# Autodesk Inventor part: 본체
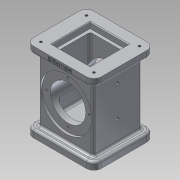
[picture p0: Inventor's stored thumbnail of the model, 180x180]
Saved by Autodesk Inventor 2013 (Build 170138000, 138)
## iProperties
Created: 2017-08
Part Number: 본체
Material: 알루미늄 6061
Document SubType Name: Modeling
Designer: Administrator
Density: 2.71 g/cm^3
Mass: 843.232 g
Surface Area: 643.489 cm^2
Volume: 311.156 cm^3
Author: Administrator
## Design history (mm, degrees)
sketch "스케치4"
  geometry: L1 (0, 0)-(-74, 0); L2 (-74, 0)-(-74, 88); L3 (-74, 88)-(0, 88); L4 (0, 88)-(0, 0)
  constraints: 8 end point, 2 parallel, 1 horizontal, 1 perpendicular
  dimensions: "d26" = 88 distance of L3.end L1.start; "d27" = 74 distance of L2.end L3.end
extrude "돌출1" new body sketch "스케치4" distance "d28" = 66; taper "d29" = 0 deg
sketch "스케치5"
  geometry: L1 (74, 0)-(0, 0) reference; L2 (74, 0)-(74, 66) reference; L3 (83, -8)-(-9, -8); L4 (-9, 74)-(83, 74); L5 (-9, 74)-(-9, -8); L6 (83, -8)-(83, 74)
  constraints: 8 end point, 1 parallel, 1 perpendicular
  dimensions: "d127" = 92 distance of L4.start L4.end; "d128" = 82 distance of L3.start L4.end; "d129" = 8 distance between parallel lines of L3 L1; "d130" = 9 distance between parallel lines of L6 L2
extrude "돌출2" join sketch "스케치5" distance "d31" = 10; taper "d32" = 0 deg
sketch "스케치6"
  geometry: L1 (0, 66)-(74, 66) reference; L2 (83, 74)-(83, -8); L3 (-9, -8)-(-9, 74); L4 (-9, 74)-(83, 74); L5 (-9, -8)-(83, -8); L6 (74, 0)-(74, 66) reference
  constraints: 8 end point, 1 parallel, 1 perpendicular
  dimensions: "d133" = 82 distance of L2.start L2.end; "d135" = 92 distance of L3.end L2.start; "d136" = 8 distance between parallel lines of L1 L4; "d142" = 9 distance between parallel lines of L2 L6
extrude "돌출3" join sketch "스케치6" distance "d34" = 10; taper "d35" = 0 deg
fillet "모깎기1" dims "d36" = 3, "d53" = 10
sketch "스케치7"
  geometry: L1 (0, 88)-(0, 0) reference; L2 (1, 98)-(73, 98) reference; C1 r 35 at (37, 44)
  constraints: 1 centre point
  dimensions: "d37" = 37 distance from line of L1 C1.centre; "d38" = 54 distance from line of L2 C1.centre; "d39" = 70 diameter of C1
extrude "돌출4" cut sketch "스케치7" distance "d40" = 3; taper "d41" = 0 deg
sketch "스케치8"
  geometry: C1 r 35 at (37, -44) reference; C2 r 35 at (37, -44)
  constraints: 1 centre point, 1 coincident, 1 concentric
extrude "돌출5" cut sketch "스케치8" distance "d42" = 3; taper "d43" = 0 deg
sketch "스케치9"
  geometry: C1 r 35 at (0, 0) reference; C2 r 24 at (0, 0); 1 further point
  constraints: 1 centre point, 1 coincident
  dimensions: "d44" = 48 diameter of C2
extrude "돌출6" cut sketch "스케치9" stored distance "d46" = 3; taper "d47" = 0 deg
sketch "스케치10"
  geometry: L1 (73, 74)-(1, 74) reference; L2 (11, 59)-(63, 59); L3 (63, 59)-(63, 7); L4 (63, 7)-(11, 7); L5 (11, 7)-(11, 59); L6 (-9, 64)-(-9, 2) reference; 1 further point
  constraints: 8 end point, 2 parallel, 1 horizontal, 1 perpendicular
  dimensions: "d48" = 52 distance of L2.start L2.end; "d50" = 52 distance of L2.end L3.end; "d126" = 15 distance between parallel lines of L2 L1; "d131" = 20 distance between parallel lines of L6 L5
extrude "돌출7" cut sketch "스케치10" distance "d54" = 8; taper "d55" = 0 deg
sketch "스케치11"
  geometry: L1 (11, 59)-(63, 59) reference; L2 (11, 7)-(11, 59) reference; L3 (63, 7)-(11, 7) reference; L4 (63, 59)-(63, 7) reference; L5 (59, 55)-(15, 55); L6 (15, 55)-(15, 11); L7 (15, 11)-(59, 11); L8 (59, 11)-(59, 55); 1 further point
  constraints: 8 end point, 3 other
  dimensions: "d56" = 4 distance between parallel lines of L5 L1
extrude "돌출8" cut sketch "스케치11" distance "d57" = 74; taper "d58" = 0 deg
fillet "모깎기2" dims "d59" = 3
sketch "스케치12"
  geometry: 20 further points
  constraints: 4 coincident, 4 other
hole "구멍1" sketch "스케치12" at (1, 64), (73, 64), (73, 2), (1, 2) diameter "d60" = 3.242; stored, may be unused: countersink angle "d64" = 90 deg, drill point angle "d66" = 118 deg; dims "d61" = 4, "d62" = 4, "d63" = 2, "d65" = 6
sketch "스케치13"
  geometry: 20 further points
  constraints: 4 coincident, 4 other
hole "구멍2" sketch "스케치13" at (1, 64), (73, 64), (73, 2), (1, 2) diameter "d67" = 3.242; stored, may be unused: countersink angle "d71" = 90 deg, drill point angle "d73" = 118 deg; dims "d68" = 4, "d69" = 4, "d70" = 2, "d72" = 6
sketch "스케치14" dims "d74" = 58
  geometry: C1 r 24 at (0, 0) reference; C2 r 35 at (0, 0) reference; 3 further points
  constraints: 1 coincident, 1 vertical alignment, 2 other
  dimensions: "d76" = 0 horizontal distance of C1.centre point (0, 29)
hole "구멍3" sketch "스케치14" at (0, 29) diameter "d77" = 3.242; stored, may be unused: countersink angle "d81" = 90 deg, drill point angle "d83" = 118 deg; dims "d78" = 4, "d79" = 4, "d80" = 2, "d82" = 6
chamfer "모따기1" distance "d87" = 1; stored, may be unused: second distance "d88" = 2, angle "d89" = 45 deg
sketch "스케치15" dims "d90" = 58
  geometry: C1 r 24 at (0, 0) reference; C2 r 35 at (0, 0) reference; 3 further points
  constraints: 1 coincident, 1 vertical alignment, 2 other
  dimensions: "d92" = 0 horizontal distance of C1.centre point (0, -29)
hole "구멍4" sketch "스케치15" at (0, -29) diameter "d93" = 3.242; stored, may be unused: countersink angle "d97" = 90 deg, drill point angle "d99" = 118 deg; dims "d94" = 4, "d95" = 4, "d96" = 2, "d98" = 6
sketch "스케치16"
  geometry: L1 (88, 0)-(0, 0) reference; L2 (98, 64)-(98, 2) reference; 2 further points
  dimensions: "d100" = 33 distance from line of point (18, 33) L1; "d101" = 33 distance from line of L1 point (60, 33); "d102" = 38 distance from line of L2 point (60, 33); "d103" = 42 distance of point (60, 33) point (18, 33)
hole "구멍5" sketch "스케치16" at (18, 33), (60, 33) diameter "d104" = 4.134; stored, may be unused: countersink angle "d108" = 90 deg, drill point angle "d110" = 118 deg; dims "d105" = 4, "d106" = 4, "d107" = 2, "d109" = 20
sketch "스케치17"
  geometry: L1 (83, 2)-(83, 64) reference; L2 (61, 9)-(13, 9); L3 (13, 9)-(13, 57); L4 (13, 57)-(61, 57); L5 (61, 57)-(61, 9); L6 (1, -8)-(73, -8) reference
  constraints: 8 end point, 2 parallel, 1 horizontal, 1 perpendicular
  dimensions: "d111" = 48 distance of L2.start L2.end; "d113" = 48 distance of L2.end L3.end; "d115" = 22 distance between parallel lines of L5 L1; "d137" = 17 distance between parallel lines of L6 L2
extrude "돌출9" cut sketch "스케치17" distance "d116" = 16; taper "d117" = 0 deg
fillet "모깎기3" dims "d118" = 3
sketch "스케치18"
  geometry: L1 (0, 0)-(72, 0) reference; L2 (16.555, 0.528)-(55.445, 0.528); L3 (55.445, 0.528)-(55.445, -8.528); L4 (55.445, -8.528)-(16.555, -8.528); L5 (16.555, -8.528)-(16.555, 0.528); L6 (36, 0.528)-(36, -8.528); L7 (16.555, -4)-(55.445, -4); L8 (-10, 0)-(-10, -10) reference; 1 further point
  constraints: 4 end point, 4 midpoint, 2 other
  dimensions: "d120" = 4 distance between parallel lines of L7 L1; "d121" = 38.88974 distance of L2.start L2.end; "d122" = 9.05651 distance of L2.end L3.end; "d132" = 46 distance between parallel lines of L6 L8
feature "엠보싱1" sketch "스케치18" dims "d26" = 88, "d27" = 74, "d123" = 0.5, "d124" = 0
fillet "모깎기5" dims "d138" = 3
node "솔리드1"
pattern_circular "원형 패턴1" dims angle "d85" = 360 deg
pattern_circular "원형 패턴2" dims angle "d140" = 360 deg
node "투영된 루프1"
